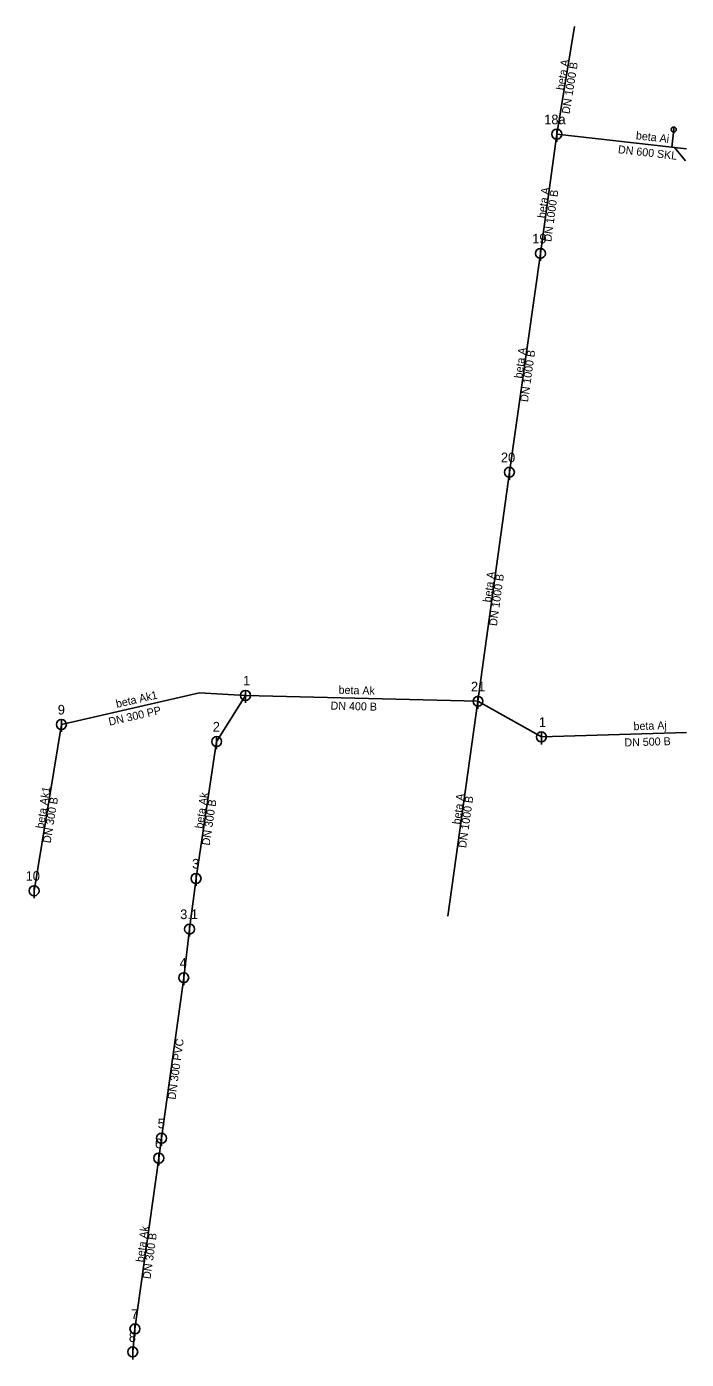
# Model space of a CAD drawing. Extents: x -463672 to -463539, y -1094894 to -1094627.
import ezdxf

# ---------------------------------------------------------------- set-up
doc = ezdxf.new("R2010")
doc.units = 0
for name, color, linetype in [('_pripojka_kanal_destova_prevzato_z_dokumentace_', 7, 'Continuous'), ('_pripojka_kanal_jednotna_prevzato_z_dokumentace_', 7, 'Continuous'), ('_stoka_jednotna_smvak_prevzato_z_dokumentace_', 7, 'Continuous'), ('_stoka_jednotna_smvak_priblizne_', 7, 'Continuous'), ('Default', 7, 'Continuous'), ('MoLevel 1', 7, 'Continuous'), ('MoLevel 119', 7, 'Continuous'), ('MoLevel 120', 7, 'Continuous'), ('MoLevel 2', 7, 'Continuous'), ('MoLevel 57', 7, 'Continuous'), ('MoLevel 68', 7, 'Continuous'), ('MoLevel 69', 7, 'Continuous')]:
    doc.layers.add(name, color=color, linetype=linetype)

# ---------------------------------------------------------------- blocks, each defined once
blk = doc.blocks.new('_sachta_kanal_prip_')
at = {"layer": 'Default'}
blk.add_line((0, 0.00005), (0, -0.000075), dxfattribs=at)
blk.add_circle((0, 0), 0.00005, dxfattribs=at)
blk = doc.blocks.new('_sachta_kanal_prevzato_z_dokumentace_')
at = {"layer": 'Default'}
blk.add_line((0, 0.00005), (0, -0.000075), dxfattribs=at)
blk.add_circle((0, 0), 0.00005, dxfattribs=at)

msp = doc.modelspace()

# ---------------------------------------------------------------- linework, layer by layer
at = {"layer": '_pripojka_kanal_destova_prevzato_z_dokumentace_'}
msp.add_line((-463539.32, -1094654.2), (-463541.52, -1094651.54), dxfattribs=at)
at = {"layer": '_pripojka_kanal_jednotna_prevzato_z_dokumentace_'}
msp.add_line((-463541.69, -1094647.93), (-463542.09, -1094651.48), dxfattribs=at)
at = {"layer": '_stoka_jednotna_smvak_prevzato_z_dokumentace_'}
for p, q in [((-463565.16, -1094648.86), (-463561.61, -1094627.3)), ((-463568.44, -1094672.76), (-463565.16, -1094648.86)), ((-463574.67, -1094716.63), (-463568.44, -1094672.76)), ((-463580.97, -1094762.56), (-463574.67, -1094716.63)), ((-463627.63, -1094761.39), (-463580.97, -1094762.56)), ((-463587, -1094805.65), (-463580.97, -1094762.56)), ((-463568.25, -1094769.7), (-463580.97, -1094762.56)), ((-463670.06, -1094800.55), (-463664.58, -1094767.21)), ((-463539.15, -1094768.85), (-463568.25, -1094769.7)), ((-463644.49, -1094850.16), (-463640.03, -1094817.98)), ((-463645.04, -1094854.16), (-463644.49, -1094850.16)), ((-463649.82, -1094888.4), (-463645.04, -1094854.16)), ((-463650.27, -1094893), (-463649.82, -1094888.4))]:
    msp.add_line(p, q, dxfattribs=at)
for points in [[(-463539.15, -1094651.82), (-463541.52, -1094651.54), (-463542.09, -1094651.48), (-463565.16, -1094648.86)], [(-463633.42, -1094770.63), (-463633.41, -1094770.58), (-463627.63, -1094761.39)], [(-463637.56, -1094798.09), (-463637.55, -1094797.98), (-463633.42, -1094770.63)], [(-463638.86, -1094808.23), (-463638.85, -1094808.17), (-463637.56, -1094798.09)], [(-463640.03, -1094817.98), (-463640.03, -1094817.98), (-463638.86, -1094808.23)]]:
    msp.add_lwpolyline(points, dxfattribs=at)
at = {"layer": '_stoka_jednotna_smvak_priblizne_'}
msp.add_lwpolyline([(-463664.58, -1094767.21), (-463636.84, -1094760.87), (-463627.63, -1094761.39)], dxfattribs=at)

# ---------------------------------------------------------------- block references
at = {"layer": 'MoLevel 119', "xscale": 20000, "yscale": 20000}
for p in [(-463565.16, -1094648.86), (-463568.44, -1094672.76), (-463574.67, -1094716.63), (-463627.63, -1094761.39), (-463580.97, -1094762.56), (-463664.58, -1094767.21), (-463633.42, -1094770.63), (-463568.25, -1094769.7), (-463637.56, -1094798.09), (-463670.06, -1094800.55), (-463638.86, -1094808.23), (-463640.03, -1094817.98), (-463644.49, -1094850.16), (-463645.04, -1094854.16), (-463649.82, -1094888.4), (-463650.27, -1094893)]:
    msp.add_blockref('_sachta_kanal_prevzato_z_dokumentace_', p, dxfattribs=at)
at = {"layer": 'MoLevel 57', "xscale": 10000, "yscale": 10000}
msp.add_blockref('_sachta_kanal_prip_', (-463541.69, -1094647.93), dxfattribs=at)

# ---------------------------------------------------------------- texts
at = {"layer": 'MoLevel 1'}
msp.add_text('DN 300 PP', height=1.605, rotation=12.8725, dxfattribs=at).set_placement((-463654.92, -1094767.47))
at = {"layer": 'MoLevel 120'}
for s, height, p in [('18a', 1.926, (-463567.68, -1094646.86)), ('19', 1.926, (-463570.09, -1094670.76)), ('20', 1.926, (-463576.37, -1094714.63)), ('1', 1.93, (-463628.13, -1094759.39)), ('21', 1.926, (-463582.39, -1094760.56)), ('9', 1.93, (-463665.31, -1094765.21)), ('2', 1.93, (-463634.2, -1094768.63)), ('1', 1.93, (-463568.75, -1094767.7)), ('3', 1.93, (-463638.34, -1094796.09)), ('10', 1.926, (-463671.76, -1094798.55)), ('3.1', 1.926, (-463640.74, -1094806.23)), ('4', 1.93, (-463640.86, -1094815.98)), ('5', 1.93, (-463645.27, -1094848.16)), ('6', 1.93, (-463645.82, -1094852.16)), ('7', 1.93, (-463650.6, -1094886.4)), ('8', 1.93, (-463651.05, -1094891))]:
    msp.add_text(s, height=height, dxfattribs=at).set_placement(p)
at = {"layer": 'MoLevel 2'}
msp.add_text('beta Ak1', height=1.605, rotation=12.8725, dxfattribs=at).set_placement((-463653.45, -1094763.89))
at = {"layer": 'MoLevel 68'}
for s, rotation, p in [('DN 1000 B', 80.6502, (-463562.61, -1094644.89)), ('DN 600 SKL', 353.5208, (-463552.94, -1094652.66)), ('DN 1000 B', 82.1856, (-463566.27, -1094670.51)), ('DN 1000 B', 81.9147, (-463570.95, -1094702.64)), ('DN 1000 B', 82.1934, (-463577.18, -1094747.54)), ('DN 400 B', 358.5636, (-463610.57, -1094764.22)), ('DN 500 B', 1.6788, (-463551.57, -1094771.62)), ('DN 300 B', 80.6659, (-463666.75, -1094791.09)), ('DN 300 B', 81.4082, (-463634.84, -1094791.56)), ('DN 1000 B', 82.0327, (-463583.36, -1094792.05)), ('DN 300 PVC', 82.0996, (-463641.7, -1094842.49)), ('DN 300 B', 82.0471, (-463646.7, -1094878.47))]:
    msp.add_text(s, height=1.605, rotation=rotation, dxfattribs=at).set_placement(p)
at = {"layer": 'MoLevel 69'}
for s, rotation, p in [('beta A', 80.6502, (-463563.71, -1094640.12)), ('beta Ai', 353.5208, (-463549.34, -1094649.86)), ('beta A', 82.1856, (-463567.46, -1094665.77)), ('beta A', 81.9147, (-463572.13, -1094697.9)), ('beta A', 82.1934, (-463578.37, -1094742.81)), ('beta Ak', 358.5636, (-463608.96, -1094761.06)), ('beta Aj', 1.6788, (-463549.74, -1094768.36)), ('beta Ak1', 80.6659, (-463668.16, -1094788.17)), ('beta Ak', 81.4082, (-463636.19, -1094788.17)), ('beta A', 82.0327, (-463584.55, -1094787.32)), ('beta Ak', 82.0471, (-463648.07, -1094875.1))]:
    msp.add_text(s, height=1.605, rotation=rotation, dxfattribs=at).set_placement(p)

doc.saveas('drawing.dxf')
